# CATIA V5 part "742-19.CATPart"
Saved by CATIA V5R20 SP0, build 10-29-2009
Part number: 742-19
Bounding box of the stored display mesh (mm): x -20 to 21.5, y -20 to 20, z -23 to 36
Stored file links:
  C:\Users\Utente\Desktop\IO LAVORO\3D X SITO CF\X SITO\742\742-19.CATPart
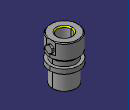
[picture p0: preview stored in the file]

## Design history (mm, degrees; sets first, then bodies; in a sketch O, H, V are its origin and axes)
Set1
  DatumSurface1 to DatumSurface38 "742-19"
Body1 (main body)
